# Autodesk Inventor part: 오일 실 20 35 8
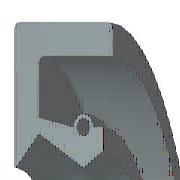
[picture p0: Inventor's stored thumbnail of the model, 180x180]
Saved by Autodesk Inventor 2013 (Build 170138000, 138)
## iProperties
Created: 2012-02
Part Number: 오일 실 20 35 8
Material: 고무
Description: 오일-실
Document SubType Name: Modeling
Standard: KS B 2804
Designer: mduedu
Standards Organization: KS
Language: ko-KR
Size Designation: D - 20 35 8
Categories: <MemberInstance><Categories><Category DisplayName="샤프트 부품" InternalName="7f7aeb1f-a693-4053-b835-cee3144e0d98" Mnemonic="SHFT"><Category DisplayName="실링" Intern
Density: 0.93 g/cm^3
Mass: 2.54606 g
Surface Area: 35.9421 cm^2
Volume: 2.7377 cm^3
IsCustomPart: 1
Author: mduedu
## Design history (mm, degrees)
revolve "본체" stored, may be unused: angle "d17" = 90 deg
revolve "스프링1" stored, may be unused: angle "d18" = 90 deg
body "Solid1"
sketch "스케치1"
  geometry: L1 (0, 17.5)-(8, 17.5); L2 (8, 15.75)-(1.75, 15.75); L3 (1.75, 11.75)-(4.9, 10); L4 (4.9, 10)-(0, 10); L5 (0, 0)-(9.586, 0) reference; L6 (4.9, 10)-(6.3, 10.875); L7 (0, 18)-(0, -3) reference; L8 (-1.941, 0)-(11.507, 0) reference; L9 (4.2, 12.1)-(1.75, 12.71); L10 (1.75, 12.71)-(1.75, 15.75); L11 (0, 17.5)-(0, 10.088); L12 (4.9, 10)-(0, 10); L13 (1.75, 11.75)-(0.152, 10.028); L14 (8, 17.5)-(8, 15.75); L15 (5.6, 12.1)-(6.3, 12.1); L16 (6.3, 12.1)-(6.3, 10.875); C1 r 0.455 at (4.9, 12.1); A1 r 0.7 centre (4.9, 12.1) between (5.6, 12.1) and (4.2, 12.1); A2 r 0.088 centre (0.088, 10.088) between (0, 10.088) and (0.152, 10.028); 1 further point
  constraints: 28 end point, 5 horizontal alignment, 5 point on line, 4 point on circle, 4 vertical alignment, 3 centre point, 3 tangent, 2 collinear, 2 horizontal, 2 perpendicular, 1 coincident, 1 parallel
  dimensions: "d0" = 35 diameter of L1 L5 (= SD2); "d1" = 1.75 distance of L1.end L2.start (= SD); "d2" = 0.91 diameter of C1 (= SPDI); "d3" = 1.4 diameter of A1 (= SPDA); "d4" = 20 diameter of L3.end L5 (= NND); "d5" = 23.5 diameter of L3.start L5 (= TKDM); "d7" = 25.42 diameter of L9.end L5 (= TKDM + 0.24 x SWDT); "d8" = 1.75 distance between parallel lines of L11 L10 (= SD); "d9" = 4.9 distance from line of L11 C1.centre (= SPDST); "d10" = 24.2 diameter of C1.centre L5 (= HLDM); "d11" = 0.0875 radius of A2 (= 0.25 x LAB); "d12" = 6.3 distance between parallel lines of L11 L16 (= SDI); "d13" = 21.75 diameter of L6.end L5 (= ABDM); "d14" = 8 distance from line of L11 L1.end (= SWDT)
fillet "모깎기1" dims "d6" = 0.3 (= RR)
other parameters: "SD2" = 35 [user parameter; used in 1 equation term], "SWDT" = 8 [user parameter; used in 2 equation terms], "RR" = 0.3 [user parameter; used in 1 equation term], "SD" = 1.75 [user parameter; used in 2 equation terms], "NND" = 20 [user parameter; used in 1 equation term], "SPDA" = 1.4 [user parameter; used in 1 equation term], "SPDI" = 0.91 [user parameter; used in 1 equation term], "TKDM" = 23.5 [user parameter; used in 2 equation terms], "HLDM" = 24.2 [user parameter; used in 1 equation term], "ABDM" = 21.75 [user parameter; used in 1 equation term], "SDI" = 6.3 [user parameter; used in 1 equation term], "SPDST" = 4.9 [user parameter; used in 1 equation term], "LAB" = 0.35 [user parameter; used in 1 equation term], "d15" = 0, "d16" = 0, "d19" = 0
